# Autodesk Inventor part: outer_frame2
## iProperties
Shininess: 64.0
Length Units: 11269
Angle Units: 11279
Time Units: 11290
Mass Units: 11283
Length Display Precision: 3
Angle Display Precision: 2
Compacted: True
Part Number: outer_frame2
Document SubType Name: Modeling
Created: 2003-02
Material: Standard
Designer: hofer_a
Density: 0.0
Volumn: 0.0
Area: 0.0
PropertySet Name: Model Information
Control State: 0
Master: False
Checked Out: False
Author: hofer_a
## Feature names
1. Extrusion3
2. Fillet1
3. Chamfer3
4. Hole5
5. Fillet4
6. Extrusion9
7. Extrusion10
8. Hole6
9. Chamfer4
10. Chamfer8
11. Hole7
12. Chamfer10
13. Hole8
14. Hole9
15. Hole10
16. Fillet5
17. Fillet6
